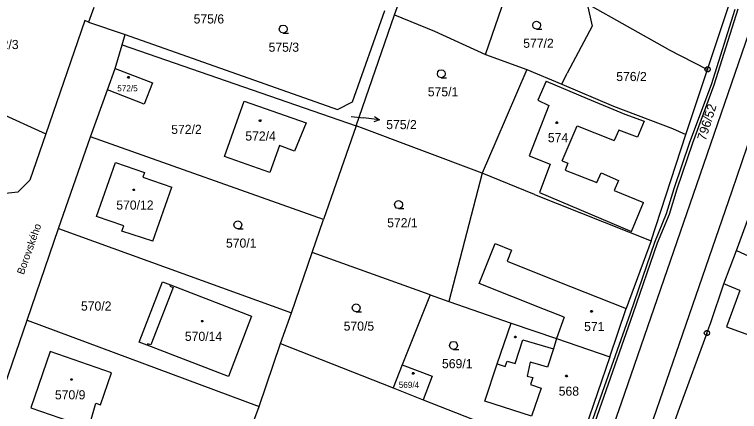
# Model space of a CAD drawing. Extents: x -759060 to -757386, y -1172273 to -1170948.
# Drawn here: x -758247.7 to -758112.4, y -1171652.9 to -1171578.9 of the extents above; entities that cross this region are included whole.
import ezdxf

# ---------------------------------------------------------------- set-up
doc = ezdxf.new("R2010")
doc.units = 0
for name, color, linetype in [('Vrstva 1', 7, 'Continuous'), ('Vrstva 12', 7, 'Continuous'), ('Vrstva 13', 7, 'Continuous'), ('Vrstva 2', 7, 'Continuous'), ('Vrstva 3', 7, 'Continuous'), ('Vrstva 4', 7, 'Continuous'), ('Vrstva 5', 7, 'Continuous'), ('Vrstva 7', 7, 'Continuous'), ('Vrstva 8', 7, 'Continuous')]:
    doc.layers.add(name, color=color, linetype=linetype)

msp = doc.modelspace()

# ---------------------------------------------------------------- linework, layer by layer
at = {"layer": 'Vrstva 1'}
for p, q in [((-758176.78, -1171578.92), (-758166.03, -1171547.74)), ((-758097.73, -1171564.24), (-758113.85, -1171611.78)), ((-758159.83, -1171586.32), (-758154.38, -1171570.54)), ((-758232.92, -1171577.54), (-758233.9, -1171580.26)), ((-758140.85, -1171576.84), (-758139.91, -1171581.01)), ((-758125.77, -1171585.32), (-758140.85, -1171576.84)), ((-758118.37, -1171589.09), (-758114.39, -1171577.18)), ((-758184.64, -1171595.16), (-758178.62, -1171578.14)), ((-758183.99, -1171599.63), (-758176.78, -1171578.92)), ((-758176.78, -1171578.92), (-758169.36, -1171581.99)), ((-758234.59, -1171579.96), (-758241.88, -1171601.11)), ((-758233.9, -1171580.26), (-758234.59, -1171579.96)), ((-758233.9, -1171580.26), (-758227.06, -1171582.57)), ((-758139.91, -1171581.01), (-758144.57, -1171589.77)), ((-758227.6, -1171584.51), (-758227.06, -1171582.57)), ((-758227.06, -1171582.57), (-758187.43, -1171596.6)), ((-758169.36, -1171581.99), (-758159.83, -1171586.32)), ((-758110.67, -1171582.26), (-758120.46, -1171610.64)), ((-758228.94, -1171588.9), (-758227.6, -1171584.51)), ((-758227.6, -1171584.51), (-758183.99, -1171599.63)), ((-758125.77, -1171585.32), (-758118.37, -1171589.09)), ((-758159.83, -1171586.32), (-758152.08, -1171589.1)), ((-758230.39, -1171592.93), (-758228.94, -1171588.9)), ((-758228.94, -1171588.9), (-758221.97, -1171591.57)), ((-758152.08, -1171589.1), (-758157.89, -1171602.55)), ((-758152.08, -1171589.1), (-758145.59, -1171591.85)), ((-758145.59, -1171591.85), (-758144.57, -1171589.77)), ((-758122.44, -1171601.25), (-758118.37, -1171589.09)), ((-758262.54, -1171591.74), (-758241.88, -1171601.11)), ((-758221.97, -1171591.57), (-758223.51, -1171595.58)), ((-758145.59, -1171591.85), (-758135.95, -1171595.94)), ((-758233.55, -1171601.64), (-758230.39, -1171592.93)), ((-758223.51, -1171595.58), (-758230.39, -1171592.93)), ((-758208.5, -1171605.36), (-758204.87, -1171595.01)), ((-758204.87, -1171595.01), (-758193.29, -1171599.08)), ((-758187.43, -1171596.6), (-758184.64, -1171595.16)), ((-758135.95, -1171595.94), (-758124.92, -1171600.11)), ((-758193.29, -1171599.08), (-758195.44, -1171604.37)), ((-758183.99, -1171599.63), (-758190.03, -1171617.06)), ((-758160.44, -1171608.45), (-758183.99, -1171599.63)), ((-758124.92, -1171600.11), (-758122.44, -1171601.25)), ((-758241.88, -1171601.11), (-758244.84, -1171609.72)), ((-758239.48, -1171618.73), (-758233.55, -1171601.64)), ((-758190.03, -1171617.06), (-758233.55, -1171601.64)), ((-758128.93, -1171621.09), (-758122.44, -1171601.25)), ((-758198.29, -1171603.29), (-758200.06, -1171608.33)), ((-758195.44, -1171604.37), (-758198.29, -1171603.29)), ((-758157.89, -1171602.55), (-758160.44, -1171608.45)), ((-758200.06, -1171608.33), (-758208.5, -1171605.36)), ((-758232.39, -1171616.51), (-758228.87, -1171606.43)), ((-758228.87, -1171606.43), (-758223.44, -1171608.31)), ((-758223.44, -1171608.31), (-758223.74, -1171609.17)), ((-758160.44, -1171608.45), (-758166.65, -1171632.35)), ((-758150.71, -1171612.45), (-758160.44, -1171608.45)), ((-758244.84, -1171609.72), (-758247.12, -1171611.98)), ((-758223.74, -1171609.17), (-758218.35, -1171611.03)), ((-758221.9, -1171621.14), (-758218.35, -1171611.03)), ((-758120.46, -1171610.64), (-758134.53, -1171651.36)), ((-758247.12, -1171611.98), (-758249.96, -1171612.3)), ((-758150.71, -1171612.45), (-758128.93, -1171621.09)), ((-758113.85, -1171611.78), (-758123.09, -1171638.47)), ((-758113.01, -1171622.85), (-758109.79, -1171614.21)), ((-758227.3, -1171618.25), (-758232.39, -1171616.51)), ((-758227.66, -1171619.24), (-758227.3, -1171618.25)), ((-758192.17, -1171623.26), (-758190.03, -1171617.06)), ((-758245.38, -1171635.86), (-758239.48, -1171618.73)), ((-758239.48, -1171618.73), (-758196.05, -1171634.49)), ((-758221.9, -1171621.14), (-758227.66, -1171619.24)), ((-758128.93, -1171621.09), (-758133.6, -1171633.7)), ((-758196.05, -1171634.49), (-758192.17, -1171623.26)), ((-758170.14, -1171631.13), (-758192.17, -1171623.26)), ((-758115.33, -1171629.09), (-758113.01, -1171622.85)), ((-758113.01, -1171622.85), (-758095.48, -1171631.06)), ((-758224.46, -1171639.93), (-758220.12, -1171628.68)), ((-758220.12, -1171628.68), (-758218.63, -1171629.24)), ((-758117.78, -1171636.28), (-758115.33, -1171629.09)), ((-758112.37, -1171630.3), (-758115.33, -1171629.09)), ((-758218.63, -1171629.24), (-758203.47, -1171635.1)), ((-758170.14, -1171631.13), (-758175.38, -1171644.21)), ((-758170.14, -1171631.13), (-758166.65, -1171632.35)), ((-758166.65, -1171632.35), (-758155.05, -1171636.41)), ((-758198.07, -1171640.23), (-758196.05, -1171634.49)), ((-758136.65, -1171642.67), (-758133.6, -1171633.7)), ((-758251.29, -1171652.99), (-758245.38, -1171635.86)), ((-758245.38, -1171635.86), (-758202.08, -1171651.93)), ((-758203.47, -1171635.1), (-758207.8, -1171646.36)), ((-758157.63, -1171644.02), (-758155.05, -1171636.41)), ((-758155.05, -1171636.41), (-758146.55, -1171639.29)), ((-758118.5, -1171638.25), (-758117.78, -1171636.28)), ((-758117.78, -1171636.28), (-758117.78, -1171636.28)), ((-758123.09, -1171638.47), (-758129.77, -1171657.77)), ((-758118.5, -1171638.25), (-758123.68, -1171652.34)), ((-758118.5, -1171638.25), (-758118.5, -1171638.25)), ((-758222.99, -1171640.49), (-758224.46, -1171639.93)), ((-758146.55, -1171639.29), (-758136.65, -1171642.67)), ((-758207.8, -1171646.36), (-758222.99, -1171640.49)), ((-758202.08, -1171651.93), (-758198.07, -1171640.23)), ((-758198.07, -1171640.23), (-758177.07, -1171648.49)), ((-758241.05, -1171641.72), (-758244.67, -1171652.18)), ((-758229.6, -1171645.67), (-758241.05, -1171641.72)), ((-758136.65, -1171642.67), (-758141.56, -1171657.09)), ((-758159.94, -1171650.96), (-758157.63, -1171644.02)), ((-758175.38, -1171644.21), (-758177.07, -1171648.49)), ((-758175.38, -1171644.21), (-758169.76, -1171646.31)), ((-758231.65, -1171651.63), (-758229.6, -1171645.67)), ((-758169.76, -1171646.31), (-758171.48, -1171650.69)), ((-758177.07, -1171648.49), (-758171.48, -1171650.69)), ((-758171.48, -1171650.69), (-758152.67, -1171658.04)), ((-758233.41, -1171654.38), (-758232.51, -1171651.34)), ((-758232.51, -1171651.34), (-758231.65, -1171651.63)), ((-758203.79, -1171656.58), (-758202.08, -1171651.93)), ((-758151.23, -1171653.75), (-758159.94, -1171650.96)), ((-758134.53, -1171651.36), (-758149.82, -1171695.47)), ((-758244.67, -1171652.18), (-758235.65, -1171655.29)), ((-758123.68, -1171652.34), (-758125.42, -1171657.08)), ((-758123.68, -1171652.34), (-758123.68, -1171652.34))]:
    msp.add_line(p, q, dxfattribs=at)
at = {"layer": 'Vrstva 12'}
for p, q in [((-758230.39, -1171592.93), (-758228.94, -1171588.9)), ((-758228.94, -1171588.9), (-758221.97, -1171591.57)), ((-758148.5, -1171591.27), (-758150.07, -1171594.84)), ((-758148.5, -1171591.27), (-758140.86, -1171594.49)), ((-758221.97, -1171591.57), (-758223.51, -1171595.58)), ((-758223.51, -1171595.58), (-758230.39, -1171592.93)), ((-758208.5, -1171605.36), (-758204.87, -1171595.01)), ((-758204.87, -1171595.01), (-758193.29, -1171599.08)), ((-758150.07, -1171594.84), (-758148.02, -1171595.81)), ((-758140.86, -1171594.49), (-758133.83, -1171597.46)), ((-758148.02, -1171595.81), (-758151.65, -1171605.24)), ((-758133.83, -1171597.46), (-758130.23, -1171598.76)), ((-758193.29, -1171599.08), (-758195.44, -1171604.37)), ((-758130.23, -1171598.76), (-758131.43, -1171601.7)), ((-758145.51, -1171606.16), (-758142.71, -1171599.6)), ((-758142.71, -1171599.6), (-758135.82, -1171602.37)), ((-758134.94, -1171600.4), (-758135.82, -1171602.37)), ((-758131.43, -1171601.7), (-758134.94, -1171600.4)), ((-758198.29, -1171603.29), (-758200.06, -1171608.33)), ((-758195.44, -1171604.37), (-758198.29, -1171603.29)), ((-758200.06, -1171608.33), (-758208.5, -1171605.36)), ((-758151.65, -1171605.24), (-758147.74, -1171606.79)), ((-758232.39, -1171616.51), (-758228.87, -1171606.43)), ((-758228.87, -1171606.43), (-758223.44, -1171608.31)), ((-758147.74, -1171606.79), (-758149.77, -1171612.04)), ((-758145.51, -1171606.16), (-758144.47, -1171606.57)), ((-758144.47, -1171606.57), (-758144.98, -1171607.87)), ((-758223.44, -1171608.31), (-758223.74, -1171609.17)), ((-758144.98, -1171607.87), (-758139.04, -1171610.18)), ((-758139.04, -1171610.18), (-758138.22, -1171608.36)), ((-758138.22, -1171608.36), (-758135.03, -1171609.8)), ((-758223.74, -1171609.17), (-758218.35, -1171611.03)), ((-758135.03, -1171609.8), (-758135.8, -1171611.66)), ((-758221.9, -1171621.14), (-758218.35, -1171611.03)), ((-758149.77, -1171612.04), (-758132.6, -1171619.29)), ((-758135.8, -1171611.66), (-758130.37, -1171613.91)), ((-758132.6, -1171619.29), (-758130.37, -1171613.91)), ((-758227.3, -1171618.25), (-758232.39, -1171616.51)), ((-758227.66, -1171619.24), (-758227.3, -1171618.25)), ((-758221.9, -1171621.14), (-758227.66, -1171619.24)), ((-758161.03, -1171629.01), (-758157.99, -1171621.58)), ((-758157.99, -1171621.58), (-758154.96, -1171622.8)), ((-758154.96, -1171622.8), (-758155.78, -1171624.86)), ((-758155.78, -1171624.86), (-758146.66, -1171628.5)), ((-758148.84, -1171633.84), (-758161.03, -1171629.01)), ((-758146.66, -1171628.5), (-758133.6, -1171633.7)), ((-758218.1, -1171629.77), (-758222.27, -1171640.47)), ((-758218.63, -1171629.24), (-758218.75, -1171629.52)), ((-758218.75, -1171629.52), (-758218.1, -1171629.77)), ((-758218.63, -1171629.24), (-758203.47, -1171635.1)), ((-758112.37, -1171630.3), (-758114.87, -1171637.08)), ((-758145.15, -1171635.31), (-758148.84, -1171633.84)), ((-758136.65, -1171642.67), (-758133.6, -1171633.7)), ((-758203.47, -1171635.1), (-758207.8, -1171646.36)), ((-758145.15, -1171635.31), (-758146.55, -1171639.29)), ((-758114.87, -1171637.08), (-758106.62, -1171640.13)), ((-758146.55, -1171639.29), (-758147.16, -1171641.17)), ((-758146.55, -1171639.29), (-758136.65, -1171642.67)), ((-758146.55, -1171639.29), (-758136.65, -1171642.67)), ((-758222.9, -1171640.24), (-758222.99, -1171640.49)), ((-758207.8, -1171646.36), (-758222.99, -1171640.49)), ((-758222.27, -1171640.47), (-758222.9, -1171640.24)), ((-758147.16, -1171641.17), (-758148.27, -1171644.6)), ((-758241.05, -1171641.72), (-758244.67, -1171652.18)), ((-758229.6, -1171645.67), (-758241.05, -1171641.72)), ((-758136.65, -1171642.67), (-758141.56, -1171657.09)), ((-758151.5, -1171643.7), (-758152.05, -1171646.29)), ((-758150.13, -1171644.08), (-758151.5, -1171643.7)), ((-758175.38, -1171644.21), (-758177.07, -1171648.49)), ((-758175.38, -1171644.21), (-758169.76, -1171646.31)), ((-758148.27, -1171644.6), (-758150.13, -1171644.08)), ((-758231.65, -1171651.63), (-758229.6, -1171645.67)), ((-758169.76, -1171646.31), (-758171.48, -1171650.69)), ((-758152.05, -1171646.29), (-758150.99, -1171646.56)), ((-758150.99, -1171646.56), (-758151.44, -1171647.85)), ((-758151.44, -1171647.85), (-758149.43, -1171648.55)), ((-758177.07, -1171648.49), (-758171.48, -1171650.69)), ((-758149.43, -1171648.55), (-758151.23, -1171653.75)), ((-758233.41, -1171654.38), (-758232.51, -1171651.34)), ((-758232.51, -1171651.34), (-758231.65, -1171651.63)), ((-758244.67, -1171652.18), (-758235.65, -1171655.29))]:
    msp.add_line(p, q, dxfattribs=at)
at = {"layer": 'Vrstva 13'}
for p, q in [((-758117.68, -1171591.88), (-758113.25, -1171577.88)), ((-758112.73, -1171577.88), (-758117.2, -1171592.04)), ((-758121.7, -1171602.67), (-758117.68, -1171591.88)), ((-758117.2, -1171592.04), (-758121.22, -1171602.83)), ((-758124.6, -1171611.29), (-758121.7, -1171602.67)), ((-758121.22, -1171602.83), (-758124.12, -1171611.45)), ((-758126.03, -1171615.96), (-758124.6, -1171611.29)), ((-758124.12, -1171611.45), (-758125.55, -1171616.12)), ((-758128.25, -1171621.3), (-758126.03, -1171615.96)), ((-758125.55, -1171616.12), (-758127.79, -1171621.48)), ((-758132.79, -1171634.54), (-758128.25, -1171621.3)), ((-758127.79, -1171621.48), (-758132.31, -1171634.7)), ((-758140.49, -1171656.38), (-758132.79, -1171634.54)), ((-758132.31, -1171634.7), (-758139.97, -1171656.42))]:
    msp.add_line(p, q, dxfattribs=at)
at = {"layer": 'Vrstva 3'}
for points in [[(-758150.27, -1171581.58), (-758150.65, -1171581.48), (-758150.92, -1171581.21), (-758151.02, -1171580.84), (-758150.92, -1171580.47), (-758150.65, -1171580.2), (-758150.28, -1171580.1), (-758149.91, -1171580.2), (-758149.64, -1171580.47), (-758149.54, -1171580.85), (-758149.64, -1171581.23), (-758149.91, -1171581.5), (-758150.29, -1171581.6), (-758149.29, -1171581.6)], [(-758197.55, -1171582.31), (-758197.93, -1171582.21), (-758198.2, -1171581.94), (-758198.3, -1171581.57), (-758198.2, -1171581.2), (-758197.93, -1171580.93), (-758197.56, -1171580.83), (-758197.19, -1171580.93), (-758196.92, -1171581.2), (-758196.82, -1171581.58), (-758196.92, -1171581.96), (-758197.19, -1171582.23), (-758197.57, -1171582.33), (-758196.57, -1171582.33)], [(-758168.06, -1171590.64), (-758168.44, -1171590.54), (-758168.71, -1171590.27), (-758168.81, -1171589.9), (-758168.71, -1171589.53), (-758168.44, -1171589.26), (-758168.07, -1171589.16), (-758167.7, -1171589.26), (-758167.43, -1171589.53), (-758167.33, -1171589.91), (-758167.43, -1171590.29), (-758167.7, -1171590.56), (-758168.08, -1171590.66), (-758167.08, -1171590.66)], [(-758176.03, -1171615.04), (-758176.41, -1171614.94), (-758176.68, -1171614.67), (-758176.78, -1171614.3), (-758176.68, -1171613.93), (-758176.41, -1171613.66), (-758176.04, -1171613.56), (-758175.67, -1171613.66), (-758175.4, -1171613.93), (-758175.3, -1171614.31), (-758175.4, -1171614.69), (-758175.67, -1171614.96), (-758176.05, -1171615.06), (-758175.05, -1171615.06)], [(-758206.02, -1171618.82), (-758206.4, -1171618.72), (-758206.67, -1171618.45), (-758206.77, -1171618.08), (-758206.67, -1171617.71), (-758206.4, -1171617.44), (-758206.03, -1171617.34), (-758205.66, -1171617.44), (-758205.39, -1171617.71), (-758205.29, -1171618.09), (-758205.39, -1171618.47), (-758205.66, -1171618.74), (-758206.04, -1171618.84), (-758205.04, -1171618.84)], [(-758183.94, -1171634.29), (-758184.32, -1171634.19), (-758184.59, -1171633.92), (-758184.69, -1171633.55), (-758184.59, -1171633.18), (-758184.32, -1171632.91), (-758183.95, -1171632.81), (-758183.58, -1171632.91), (-758183.31, -1171633.18), (-758183.21, -1171633.56), (-758183.31, -1171633.94), (-758183.58, -1171634.21), (-758183.96, -1171634.31), (-758182.96, -1171634.31)], [(-758165.79, -1171641.3), (-758166.17, -1171641.2), (-758166.44, -1171640.93), (-758166.54, -1171640.56), (-758166.44, -1171640.19), (-758166.17, -1171639.92), (-758165.8, -1171639.82), (-758165.43, -1171639.92), (-758165.16, -1171640.19), (-758165.06, -1171640.57), (-758165.16, -1171640.95), (-758165.43, -1171641.22), (-758165.81, -1171641.32), (-758164.81, -1171641.32)]]:
    msp.add_lwpolyline(points, dxfattribs=at)
at = {"layer": 'Vrstva 4'}
for p, q in [((-758148.5, -1171591.27), (-758150.07, -1171594.84)), ((-758148.5, -1171591.27), (-758140.86, -1171594.49)), ((-758150.07, -1171594.84), (-758148.02, -1171595.81)), ((-758140.86, -1171594.49), (-758133.83, -1171597.46)), ((-758148.02, -1171595.81), (-758151.65, -1171605.24)), ((-758133.83, -1171597.46), (-758130.23, -1171598.76)), ((-758130.23, -1171598.76), (-758131.43, -1171601.7)), ((-758145.51, -1171606.16), (-758142.71, -1171599.6)), ((-758142.71, -1171599.6), (-758135.82, -1171602.37)), ((-758134.94, -1171600.4), (-758135.82, -1171602.37)), ((-758131.43, -1171601.7), (-758134.94, -1171600.4)), ((-758151.65, -1171605.24), (-758147.74, -1171606.79)), ((-758147.74, -1171606.79), (-758149.77, -1171612.04)), ((-758145.51, -1171606.16), (-758144.47, -1171606.57)), ((-758144.47, -1171606.57), (-758144.98, -1171607.87)), ((-758144.98, -1171607.87), (-758139.04, -1171610.18)), ((-758139.04, -1171610.18), (-758138.22, -1171608.36)), ((-758138.22, -1171608.36), (-758135.03, -1171609.8)), ((-758135.03, -1171609.8), (-758135.8, -1171611.66)), ((-758149.77, -1171612.04), (-758132.6, -1171619.29)), ((-758135.8, -1171611.66), (-758130.37, -1171613.91)), ((-758132.6, -1171619.29), (-758130.37, -1171613.91)), ((-758161.03, -1171629.01), (-758157.99, -1171621.58)), ((-758157.99, -1171621.58), (-758154.96, -1171622.8)), ((-758154.96, -1171622.8), (-758155.78, -1171624.86)), ((-758155.78, -1171624.86), (-758146.66, -1171628.5)), ((-758148.84, -1171633.84), (-758161.03, -1171629.01)), ((-758146.66, -1171628.5), (-758133.6, -1171633.7)), ((-758218.1, -1171629.77), (-758222.27, -1171640.47)), ((-758218.63, -1171629.24), (-758218.75, -1171629.52)), ((-758218.75, -1171629.52), (-758218.1, -1171629.77)), ((-758112.37, -1171630.3), (-758114.87, -1171637.08)), ((-758145.15, -1171635.31), (-758148.84, -1171633.84)), ((-758145.15, -1171635.31), (-758146.55, -1171639.29)), ((-758114.87, -1171637.08), (-758106.62, -1171640.13)), ((-758154.31, -1171643.91), (-758152.85, -1171639.55)), ((-758152.85, -1171639.55), (-758147.16, -1171641.17)), ((-758146.55, -1171639.29), (-758147.16, -1171641.17)), ((-758222.9, -1171640.24), (-758222.99, -1171640.49)), ((-758222.27, -1171640.47), (-758222.9, -1171640.24)), ((-758147.16, -1171641.17), (-758148.27, -1171644.6)), ((-758157.63, -1171644.02), (-758156.16, -1171644.52)), ((-758156.16, -1171644.52), (-758155.75, -1171643.5)), ((-758155.75, -1171643.5), (-758154.31, -1171643.91)), ((-758151.5, -1171643.7), (-758152.05, -1171646.29)), ((-758150.13, -1171644.08), (-758151.5, -1171643.7)), ((-758148.27, -1171644.6), (-758150.13, -1171644.08)), ((-758152.05, -1171646.29), (-758150.99, -1171646.56)), ((-758150.99, -1171646.56), (-758151.44, -1171647.85)), ((-758151.44, -1171647.85), (-758149.43, -1171648.55)), ((-758149.43, -1171648.55), (-758151.23, -1171653.75))]:
    msp.add_line(p, q, dxfattribs=at)
at = {"layer": 'Vrstva 5'}
for points in [[(-758226.36, -1171590.41), (-758226.27, -1171590.56), (-758226.36, -1171590.71), (-758226.54, -1171590.71), (-758226.63, -1171590.56), (-758226.54, -1171590.41)], [(-758201.79, -1171598.51), (-758201.7, -1171598.66), (-758201.79, -1171598.81), (-758201.97, -1171598.81), (-758202.06, -1171598.66), (-758201.97, -1171598.51)], [(-758146.42, -1171598.86), (-758146.33, -1171599.01), (-758146.42, -1171599.16), (-758146.6, -1171599.16), (-758146.69, -1171599.01), (-758146.6, -1171598.86)], [(-758225.38, -1171611.4), (-758225.29, -1171611.55), (-758225.38, -1171611.7), (-758225.56, -1171611.7), (-758225.65, -1171611.55), (-758225.56, -1171611.4)], [(-758139.94, -1171634.05), (-758139.85, -1171634.2), (-758139.94, -1171634.35), (-758140.12, -1171634.35), (-758140.21, -1171634.2), (-758140.12, -1171634.05)], [(-758212.59, -1171635.89), (-758212.5, -1171636.04), (-758212.59, -1171636.19), (-758212.77, -1171636.19), (-758212.86, -1171636.04), (-758212.77, -1171635.89)], [(-758154.17, -1171638.85), (-758154.08, -1171639), (-758154.17, -1171639.15), (-758154.35, -1171639.15), (-758154.44, -1171639), (-758154.35, -1171638.85)], [(-758173.21, -1171645.61), (-758173.12, -1171645.76), (-758173.21, -1171645.91), (-758173.39, -1171645.91), (-758173.48, -1171645.76), (-758173.39, -1171645.61)], [(-758144.64, -1171646.11), (-758144.55, -1171646.26), (-758144.64, -1171646.41), (-758144.82, -1171646.41), (-758144.91, -1171646.26), (-758144.82, -1171646.11)], [(-758236.99, -1171646.77), (-758236.9, -1171646.92), (-758236.99, -1171647.07), (-758237.17, -1171647.07), (-758237.26, -1171646.92), (-758237.17, -1171646.77)]]:
    msp.add_lwpolyline(points, close=True, dxfattribs=at)
at = {"layer": 'Vrstva 7'}
for p in [(-758184.88, -1171597.86), (-758179.584, -1171598.525)]:
    msp.add_line(p, (-758182.56, -1171598.15), dxfattribs=at)
msp.add_lwpolyline([(-758180.513, -1171597.904), (-758179.584, -1171598.525), (-758180.638, -1171598.896)], dxfattribs=at)
at = {"layer": 'Vrstva 8'}
for p, q in [((-758118.49, -1171589.09), (-758118.25, -1171589.09)), ((-758118.62, -1171638.25), (-758118.38, -1171638.25))]:
    msp.add_line(p, q, dxfattribs=at)
for points in [[(-758118.22, -1171588.61), (-758117.97, -1171588.79), (-758117.87, -1171589.08), (-758117.97, -1171589.37), (-758118.22, -1171589.55), (-758118.53, -1171589.55), (-758118.78, -1171589.37), (-758118.88, -1171589.08), (-758118.78, -1171588.79), (-758118.53, -1171588.61)], [(-758118.35, -1171637.77), (-758118.1, -1171637.95), (-758118, -1171638.24), (-758118.1, -1171638.53), (-758118.35, -1171638.71), (-758118.66, -1171638.71), (-758118.91, -1171638.53), (-758119.01, -1171638.24), (-758118.91, -1171637.95), (-758118.66, -1171637.77)]]:
    msp.add_lwpolyline(points, close=True, dxfattribs=at)

# ---------------------------------------------------------------- texts
at = {"layer": 'Vrstva 2'}
for s, height, p in [('572/3', 1.7, (-758252.643, -1171585.3)), ('575/3', 1.7, (-758200.303, -1171585.8)), ('577/2', 1.7, (-758152.783, -1171585.06)), ('576/2', 1.7, (-758135.424, -1171591.27)), ('572/5', 1.14, (-758228.541, -1171593.18)), ('575/1', 1.7, (-758170.593, -1171594.12)), ('575/2', 0.1, (-758184.866, -1171597.86)), ('572/2', 1.7, (-758218.473, -1171601.13)), ('572/4', 1.7, (-758204.643, -1171602.37)), ('574', 1.7, (-758148.183, -1171602.67)), ('570/12', 1.7, (-758228.723, -1171615.24)), ('572/1', 1.7, (-758178.173, -1171618.54)), ('570/1', 1.7, (-758208.253, -1171622.33)), ('570/2', 1.7, (-758235.313, -1171634.07)), ('570/5', 1.7, (-758186.293, -1171637.81)), ('571', 1.7, (-758141.423, -1171637.89)), ('570/14', 1.7, (-758215.923, -1171639.72)), ('569/1', 1.7, (-758167.943, -1171644.81)), ('569/4', 1.14, (-758176.014, -1171648.49)), ('570/9', 1.7, (-758240.173, -1171650.62)), ('568', 1.7, (-758146.163, -1171649.94))]:
    msp.add_text(s, height=height, dxfattribs=at).set_placement(p)
msp.add_text('796/52', height=1.7, rotation=72.59375, dxfattribs=at).set_placement((-758118.757, -1171602.5))
at = {"layer": 'Vrstva 7'}
for s, p in [('575/6', (-758214.291, -1171580.53)), ('575/2', (-758178.343, -1171600.23))]:
    msp.add_text(s, height=1.7, dxfattribs=at).set_placement(p)
msp.add_text('Borovského', height=1.4, rotation=70.41651, dxfattribs=at).set_placement((-758246, -1171627.474))

doc.saveas('drawing.dxf')
